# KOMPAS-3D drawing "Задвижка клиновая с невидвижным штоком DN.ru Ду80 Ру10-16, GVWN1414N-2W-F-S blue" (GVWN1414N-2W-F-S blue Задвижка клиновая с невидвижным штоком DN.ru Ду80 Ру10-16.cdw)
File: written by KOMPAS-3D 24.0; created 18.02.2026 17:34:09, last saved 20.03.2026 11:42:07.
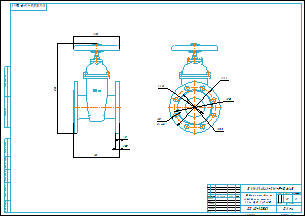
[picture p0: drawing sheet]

Document properties: Автор: R2D2; Форматы листов документа: A2; Полное имя файла: GVWN1414N-2W-F-S blue Задвижка клиновая с невидвижным штоком DN.ru Ду80 Ру10-16.m3d; Масса: 11; Наименование: Задвижка клиновая с невидвижным штоком DN.ru Ду80 Ру10-16; Количество листов документа: 1; Примечание: D040-10581

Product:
- Component [detail]: Задвижка клиновая с невидвижным штоком DN.ru Ду40-300 Ру10-16  | designation GVWN1414N-2W-F-S blue  | qty 1  | pos. 1  | Раздел спецификации: Прочие изделия; source file: исходные материалы\корпус.m3d
- Component [detail]: Фланец  | qty 2  | pos. 2  | Автор: R2D2; additional columns: Типовые; source file: исходные материалы\Фланец DN80 PN10-16 b16.5.m3d
- Component [detail]: штурвал  | qty 1  | pos. 3  | Автор: R2D2; additional columns: Типовые; source file: исходные материалы\штурвал.m3d
- Component [standard]: Hexagon socket head cap screw ISO 4762 - М8 x 12  | qty 2  | pos. 4  | Материал: Не определено (density 0 kg/m3); Масса: 0.0109; Раздел спецификации: Стандартные изделия; Рассекать на разрезах: no
- Component [standard]: Hexagon socket head cap screw ISO 4762 - М8 x 12  | qty 1  | pos. 5  | Материал: Не определено (density 0 kg/m3); Масса: 0.0109; Раздел спецификации: Стандартные изделия; Рассекать на разрезах: no
- Component [standard]: Hexagon socket head cap screw ISO 4762 - М8 x 12  | qty 1  | Материал: Не определено (density 0 kg/m3); Масса: 0.0109; Раздел спецификации: Стандартные изделия; Рассекать на разрезах: no
- Component [standard]: Hexagon socket head cap screw ISO 4762 - М6 x 10  | qty 1  | pos. 4  | Материал: Не определено (density 0 kg/m3); Масса: 0.0047; Раздел спецификации: Стандартные изделия; Рассекать на разрезах: no
- Component [standard]: Hexagon socket head cap screw ISO 4762 - М6 x 10  | qty 1  | Материал: Не определено (density 0 kg/m3); Масса: 0.0047; Раздел спецификации: Стандартные изделия; Рассекать на разрезах: no
- Part/product: Задвижка клиновая с невидвижным штоком DN.ru Ду80 Ру10-16  | designation GVWN1414N-2W-F-S blue
    Масса: 11
    Раздел спецификации: Прочие изделия
    Примечание: D040-10581

Views: Проекционный вид 2
Referenced files in E:\Работа\Зайцев\GVWN1414N-2W-F-S blue Задвижка клиновая с невидвижным штоком DN.ru Ду40-300 Ру10-16\DN80\: GVWN1414N-2W-F-S blue Задвижка клиновая с невидвижным штоком DN.ru Ду80 Ру10-16.m3d
Referenced files in E:\Работа\Зайцев\Для компаса\: чертеж DN.ru А3.cdt
Referenced files in E:\Работа\Зайцев\GVWN1414N-2W-F-S blue Задвижка клиновая с невидвижным штоком DN.ru Ду40-300 Ру10-16\DN80\исходные материалы\: корпус.m3d, Фланец DN80 PN10-16 b16.5.m3d, штурвал.m3d
Referenced files in C:\Program Files\ASCON\KOMPAS-3D v24\Libs\PolynomLib\DATA\vault\Methods\Kompas\3D\: PLib_Screw_DIN_7984_1500.m3d
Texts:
  GVWN1414N-2W-F-S blue
  чертеж DN.ru А3.cdt
  Задвижка клиновая с
  невидвижным штоком
  DN.ru Ду80 Ру10-16
  Задвижка клиновая с невидвижным штоком DN.ru Ду40-300 Ру10-16
  GVWN1414N-2W-F-S blue Задвижка клиновая с невидвижным штоком DN.ru Ду40-300 Ру10-16
  Фланец
  Твердое тело1
  штурвал
  Hexagon socket head cap screw ISO 4762 - М8 x 12
  Hexagon socket head cap screw ISO 4762 - М6 x 10
  Задвижка клиновая с невидвижным штоком DN.ru Ду80 Ру10-16
  GVWN1414N-2W-F-S blue Задвижка клиновая с невидвижным штоком DN.ru Ду80 Ру10-16
Dimensions and other numbers on the sheet: 0; 3; 4; 200; 160; 80; 18; 8 отв.; 133; 1:2; 1; 2; 11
